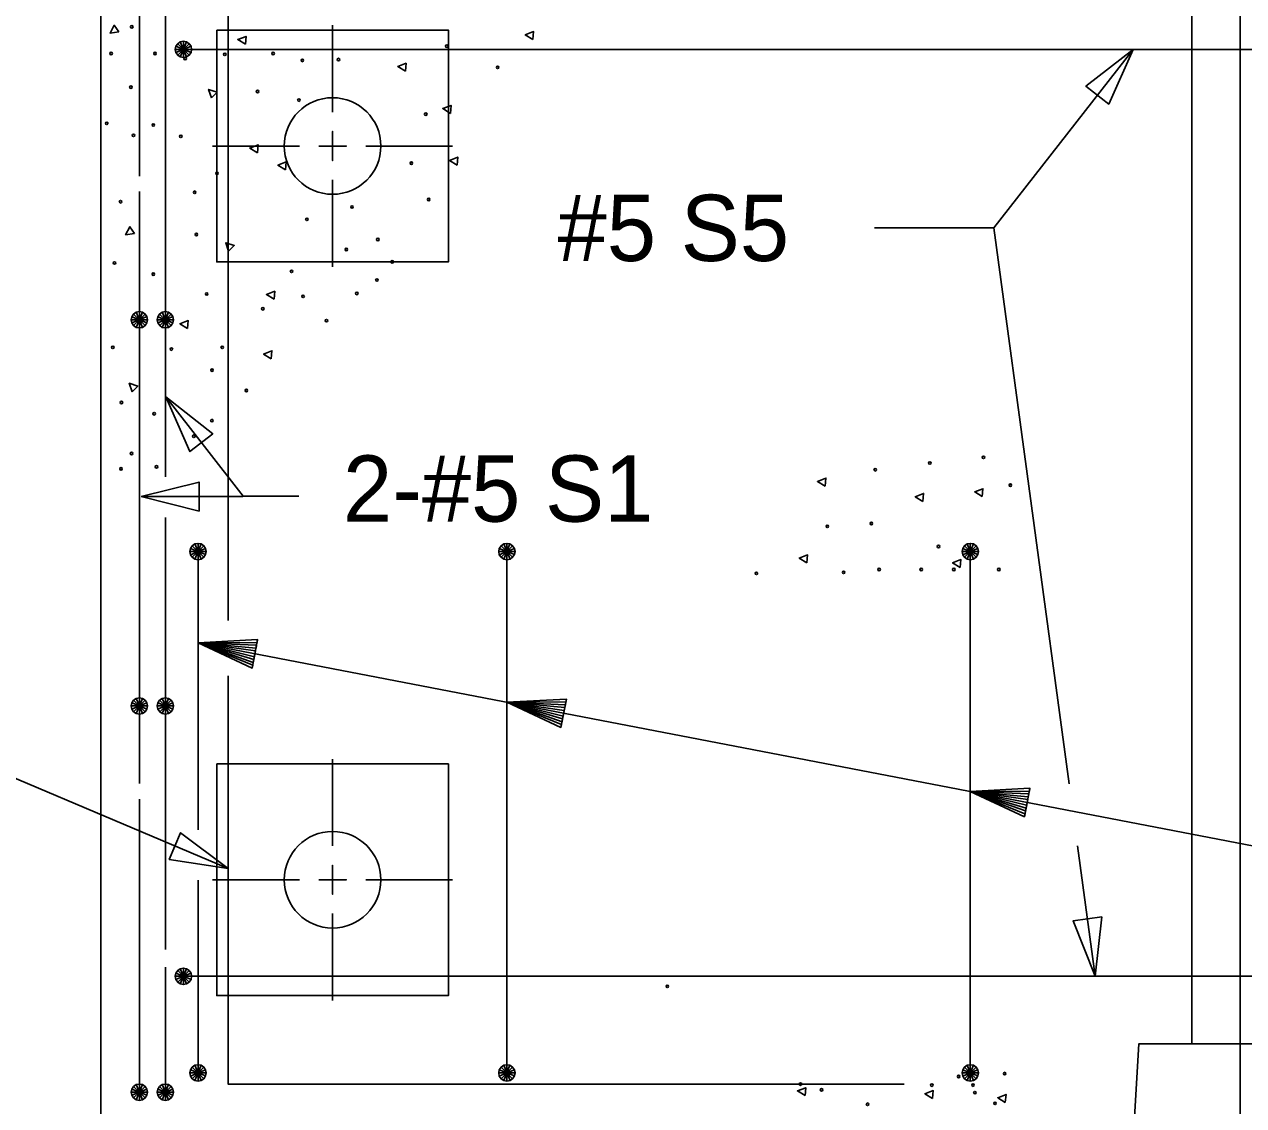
# Model space of a CAD drawing. Extents: x 0 to 177, y -1 to 127.
# Drawn here: x 141.301 to 143.931, y 47.847 to 50.18 of the extents above; entities that cross this region are included whole.
import ezdxf

# ---------------------------------------------------------------- set-up
doc = ezdxf.new("R2010")
doc.units = 0
for name, color, linetype in [('Arrowhead Terminators CELL', 7, 'Continuous'), ('Dimension Lines', 7, 'Continuous'), ('Mis Center Lines', 7, 'Continuous'), ('Rebar Lines', 7, 'Continuous'), ('Sup Concrete Girder Lines', 7, 'Continuous'), ('Sup Cored Slab Unit', 7, 'Continuous'), ('Text', 7, 'Continuous'), ('User Information Notes', 7, 'Continuous')]:
    doc.layers.add(name, color=color, linetype=linetype)

msp = doc.modelspace()

# ---------------------------------------------------------------- linework, layer by layer
at = {"layer": 'Arrowhead Terminators CELL'}
for points in [[(143.6929, 50.1259), (143.5913, 50.0466), (143.6406, 50.0081)], [(141.6057, 49.3762), (141.6577, 49.2583), (141.7071, 49.2966)], [(141.5526, 49.1609), (141.6776, 49.1297), (141.6776, 49.1922)], [(141.7406, 48.3582), (141.6377, 48.4357), (141.6133, 48.3782)], [(143.6113, 48.1259), (143.6254, 48.2539), (143.5635, 48.2455)]]:
    msp.add_lwpolyline(points, close=True, dxfattribs=at)
at = {"layer": 'Dimension Lines'}
for p, q in [((141.9656, 49.9905), (141.9656, 50.178)), ((141.894, 49.9175), (141.7065, 49.9175)), ((142.2246, 49.9175), (142.0371, 49.9175)), ((141.9656, 49.657), (141.9656, 49.8445)), ((143.3922, 49.7408), (143.5549, 48.5414)), ((141.7719, 49.1609), (141.5526, 49.1609)), ((141.9656, 48.4072), (141.9656, 48.5947)), ((143.5731, 48.4075), (143.6113, 48.1259)), ((141.894, 48.3342), (141.7065, 48.3342)), ((142.2246, 48.3342), (142.0371, 48.3342)), ((141.9656, 48.0737), (141.9656, 48.2612))]:
    msp.add_line(p, q, dxfattribs=at)
for points in [[(143.1348, 49.7408), (143.3922, 49.7408), (143.6929, 50.1259)], [(141.9357, 49.9175), (141.9656, 49.9175), (141.9955, 49.9175), (141.9656, 49.9175), (141.9656, 49.9489), (141.9656, 49.9175), (141.9656, 49.8862), (141.9656, 49.9175)], [(141.6057, 49.3762), (141.7724, 49.1616), (141.893, 49.1616)], [(141.7981, 48.8217), (141.797, 48.8156), (141.6754, 48.8453), (141.7957, 48.8094), (141.7946, 48.8033), (141.6754, 48.8453), (141.7934, 48.7972), (141.7922, 48.791), (141.6754, 48.8453), (141.804, 48.8524), (141.8029, 48.8462), (141.6754, 48.8453), (141.8016, 48.8401), (141.8005, 48.834), (141.6754, 48.8453), (141.7993, 48.8279), (141.7922, 48.791), (141.804, 48.8524), (141.6754, 48.8453), (141.7922, 48.791)], [(141.6754, 48.8453), (145.4224, 48.1242), (145.5342, 48.1242)], [(142.4644, 48.6935), (142.4633, 48.6873), (142.3417, 48.7171), (142.4621, 48.6812), (142.4609, 48.675), (142.3417, 48.7171), (142.4597, 48.6689), (142.4585, 48.6628), (142.3417, 48.7171), (142.4703, 48.7242), (142.4692, 48.718), (142.3417, 48.7171), (142.468, 48.7119), (142.4668, 48.7057), (142.3417, 48.7171), (142.4656, 48.6996), (142.4585, 48.6628), (142.4703, 48.7242), (142.3417, 48.7171), (142.4585, 48.6628)], [(140.796, 48.6638), (141.0193, 48.6638), (141.7406, 48.3582)], [(143.4644, 48.501), (143.4633, 48.4949), (143.3417, 48.5246), (143.4621, 48.4887), (143.4609, 48.4826), (143.3417, 48.5246), (143.4597, 48.4765), (143.4585, 48.4703), (143.3417, 48.5246), (143.4703, 48.5317), (143.4692, 48.5255), (143.3417, 48.5246), (143.468, 48.5194), (143.4668, 48.5133), (143.3417, 48.5246), (143.4656, 48.5072), (143.4585, 48.4703), (143.4703, 48.5317), (143.3417, 48.5246), (143.4585, 48.4703)], [(141.9357, 48.3342), (141.9656, 48.3342), (141.9955, 48.3342), (141.9656, 48.3342), (141.9656, 48.3655), (141.9656, 48.3342), (141.9656, 48.3028), (141.9656, 48.3342)]]:
    msp.add_lwpolyline(points, dxfattribs=at)
at = {"layer": 'Mis Center Lines'}
msp.add_line((143.9239, 47.6259), (143.9239, 50.6259), dxfattribs=at)
at = {"layer": 'Rebar Lines'}
for p, q in [((141.5489, 49.8527), (141.5489, 50.3759)), ((141.605, 49.2038), (141.605, 50.2242)), ((141.6439, 50.1259), (144.2689, 50.1259)), ((141.5489, 49.0027), (141.5489, 49.819)), ((141.605, 48.1837), (141.605, 49.1157)), ((141.6754, 48.4421), (141.6754, 49.0425)), ((142.3417, 47.9175), (142.3417, 49.0425)), ((143.3417, 47.9175), (143.3417, 49.0425)), ((141.5489, 48.542), (141.5489, 49.0027)), ((141.5489, 47.8759), (141.5489, 48.5083)), ((141.6754, 47.9175), (141.6754, 48.3332)), ((141.605, 47.8759), (141.605, 48.1458)), ((141.6439, 48.1259), (144.2689, 48.1259))]:
    msp.add_line(p, q, dxfattribs=at)
for points in [[(143.1991, 50.3594), (141.7406, 50.3594), (141.7406, 48.8938)], [(141.6263, 50.1259), (141.6276, 50.1326), (141.6314, 50.1383), (141.6371, 50.1422), (141.6439, 50.1435), (141.6506, 50.1422), (141.6564, 50.1383), (141.6602, 50.1326), (141.6615, 50.1259), (141.6602, 50.1191), (141.6564, 50.1134), (141.6507, 50.1096), (141.6439, 50.1082), (141.6371, 50.1096), (141.6315, 50.1134), (141.6276, 50.1191), (141.6263, 50.1259), (141.6439, 50.1259), (141.6615, 50.1259), (141.6602, 50.1326), (141.6439, 50.1259), (141.6564, 50.1383), (141.6506, 50.1422), (141.6439, 50.1259), (141.6439, 50.1435), (141.6371, 50.1422), (141.6439, 50.1259), (141.6314, 50.1383), (141.6276, 50.1326), (141.6439, 50.1259), (141.6276, 50.1191), (141.6315, 50.1134), (141.6439, 50.1259), (141.6371, 50.1096), (141.6439, 50.1082), (141.6439, 50.1259), (141.6507, 50.1096), (141.6564, 50.1134), (141.6439, 50.1259), (141.6602, 50.1191)], [(141.5313, 49.5425), (141.5326, 49.5492), (141.5364, 49.555), (141.5421, 49.5588), (141.5489, 49.5601), (141.5556, 49.5588), (141.5613, 49.555), (141.5651, 49.5493), (141.5665, 49.5425), (141.5651, 49.5358), (141.5613, 49.5301), (141.5556, 49.5262), (141.5489, 49.5249), (141.5421, 49.5262), (141.5364, 49.53), (141.5326, 49.5358), (141.5313, 49.5425), (141.5489, 49.5425), (141.5665, 49.5425), (141.5651, 49.5493), (141.5489, 49.5425), (141.5613, 49.555), (141.5556, 49.5588), (141.5489, 49.5425), (141.5489, 49.5601), (141.5421, 49.5588), (141.5489, 49.5425), (141.5364, 49.555), (141.5326, 49.5492), (141.5489, 49.5425), (141.5326, 49.5358), (141.5364, 49.53), (141.5489, 49.5425), (141.5421, 49.5262), (141.5489, 49.5249), (141.5489, 49.5425), (141.5556, 49.5262), (141.5613, 49.5301), (141.5489, 49.5425), (141.5651, 49.5358)], [(141.5874, 49.5425), (141.5887, 49.5492), (141.5925, 49.555), (141.5982, 49.5588), (141.605, 49.5601), (141.6117, 49.5588), (141.6175, 49.555), (141.6213, 49.5493), (141.6226, 49.5425), (141.6213, 49.5358), (141.6175, 49.5301), (141.6118, 49.5262), (141.605, 49.5249), (141.5982, 49.5262), (141.5926, 49.53), (141.5887, 49.5358), (141.5874, 49.5425), (141.605, 49.5425), (141.6226, 49.5425), (141.6213, 49.5493), (141.605, 49.5425), (141.6175, 49.555), (141.6117, 49.5588), (141.605, 49.5425), (141.605, 49.5601), (141.5982, 49.5588), (141.605, 49.5425), (141.5925, 49.555), (141.5887, 49.5492), (141.605, 49.5425), (141.5887, 49.5358), (141.5926, 49.53), (141.605, 49.5425), (141.5982, 49.5262), (141.605, 49.5249), (141.605, 49.5425), (141.6118, 49.5262), (141.6175, 49.5301), (141.605, 49.5425), (141.6213, 49.5358)], [(141.6578, 49.0425), (141.6591, 49.0492), (141.6629, 49.0549), (141.6686, 49.0588), (141.6754, 49.0601), (141.6821, 49.0588), (141.6878, 49.0549), (141.6916, 49.0492), (141.693, 49.0425), (141.6916, 49.0358), (141.6878, 49.03), (141.6821, 49.0262), (141.6754, 49.0248), (141.6686, 49.0262), (141.6629, 49.03), (141.6591, 49.0357), (141.6578, 49.0425), (141.6754, 49.0425), (141.693, 49.0425), (141.6916, 49.0492), (141.6754, 49.0425), (141.6878, 49.0549), (141.6821, 49.0588), (141.6754, 49.0425), (141.6754, 49.0601), (141.6686, 49.0588), (141.6754, 49.0425), (141.6629, 49.0549), (141.6591, 49.0492), (141.6754, 49.0425), (141.6591, 49.0357), (141.6629, 49.03), (141.6754, 49.0425), (141.6686, 49.0262), (141.6754, 49.0248), (141.6754, 49.0425), (141.6821, 49.0262), (141.6878, 49.03), (141.6754, 49.0425), (141.6916, 49.0358)], [(142.3241, 49.0425), (142.3254, 49.0492), (142.3292, 49.0549), (142.3349, 49.0588), (142.3417, 49.0601), (142.3484, 49.0588), (142.3541, 49.0549), (142.3579, 49.0492), (142.3593, 49.0425), (142.3579, 49.0358), (142.3541, 49.03), (142.3485, 49.0262), (142.3417, 49.0248), (142.3349, 49.0262), (142.3292, 49.03), (142.3254, 49.0357), (142.3241, 49.0425), (142.3417, 49.0425), (142.3593, 49.0425), (142.3579, 49.0492), (142.3417, 49.0425), (142.3541, 49.0549), (142.3484, 49.0588), (142.3417, 49.0425), (142.3417, 49.0601), (142.3349, 49.0588), (142.3417, 49.0425), (142.3292, 49.0549), (142.3254, 49.0492), (142.3417, 49.0425), (142.3254, 49.0357), (142.3292, 49.03), (142.3417, 49.0425), (142.3349, 49.0262), (142.3417, 49.0248), (142.3417, 49.0425), (142.3485, 49.0262), (142.3541, 49.03), (142.3417, 49.0425), (142.3579, 49.0358)], [(143.3241, 49.0425), (143.3254, 49.0492), (143.3292, 49.0549), (143.3349, 49.0588), (143.3417, 49.0601), (143.3484, 49.0588), (143.3541, 49.0549), (143.3579, 49.0492), (143.3593, 49.0425), (143.3579, 49.0358), (143.3541, 49.03), (143.3485, 49.0262), (143.3417, 49.0248), (143.3349, 49.0262), (143.3292, 49.03), (143.3254, 49.0357), (143.3241, 49.0425), (143.3417, 49.0425), (143.3593, 49.0425), (143.3579, 49.0492), (143.3417, 49.0425), (143.3541, 49.0549), (143.3484, 49.0588), (143.3417, 49.0425), (143.3417, 49.0601), (143.3349, 49.0588), (143.3417, 49.0425), (143.3292, 49.0549), (143.3254, 49.0492), (143.3417, 49.0425), (143.3254, 49.0357), (143.3292, 49.03), (143.3417, 49.0425), (143.3349, 49.0262), (143.3417, 49.0248), (143.3417, 49.0425), (143.3485, 49.0262), (143.3541, 49.03), (143.3417, 49.0425), (143.3579, 49.0358)], [(141.7406, 48.7744), (141.7406, 47.8928), (143.1991, 47.8928)], [(141.5313, 48.7092), (141.5326, 48.7159), (141.5364, 48.7216), (141.5421, 48.7255), (141.5489, 48.7268), (141.5556, 48.7255), (141.5613, 48.7216), (141.5651, 48.716), (141.5665, 48.7092), (141.5651, 48.7025), (141.5613, 48.6967), (141.5556, 48.6929), (141.5489, 48.6915), (141.5421, 48.6929), (141.5364, 48.6967), (141.5326, 48.7024), (141.5313, 48.7092), (141.5489, 48.7092), (141.5665, 48.7092), (141.5651, 48.716), (141.5489, 48.7092), (141.5613, 48.7216), (141.5556, 48.7255), (141.5489, 48.7092), (141.5489, 48.7268), (141.5421, 48.7255), (141.5489, 48.7092), (141.5364, 48.7216), (141.5326, 48.7159), (141.5489, 48.7092), (141.5326, 48.7024), (141.5364, 48.6967), (141.5489, 48.7092), (141.5421, 48.6929), (141.5489, 48.6915), (141.5489, 48.7092), (141.5556, 48.6929), (141.5613, 48.6967), (141.5489, 48.7092), (141.5651, 48.7025)], [(141.5874, 48.7092), (141.5887, 48.7159), (141.5925, 48.7216), (141.5982, 48.7255), (141.605, 48.7268), (141.6117, 48.7255), (141.6175, 48.7216), (141.6213, 48.716), (141.6226, 48.7092), (141.6213, 48.7025), (141.6175, 48.6967), (141.6118, 48.6929), (141.605, 48.6915), (141.5982, 48.6929), (141.5926, 48.6967), (141.5887, 48.7024), (141.5874, 48.7092), (141.605, 48.7092), (141.6226, 48.7092), (141.6213, 48.716), (141.605, 48.7092), (141.6175, 48.7216), (141.6117, 48.7255), (141.605, 48.7092), (141.605, 48.7268), (141.5982, 48.7255), (141.605, 48.7092), (141.5925, 48.7216), (141.5887, 48.7159), (141.605, 48.7092), (141.5887, 48.7024), (141.5926, 48.6967), (141.605, 48.7092), (141.5982, 48.6929), (141.605, 48.6915), (141.605, 48.7092), (141.6118, 48.6929), (141.6175, 48.6967), (141.605, 48.7092), (141.6213, 48.7025)], [(141.6263, 48.1259), (141.6276, 48.1326), (141.6314, 48.1383), (141.6371, 48.1422), (141.6439, 48.1435), (141.6506, 48.1422), (141.6564, 48.1383), (141.6602, 48.1326), (141.6615, 48.1259), (141.6602, 48.1191), (141.6564, 48.1134), (141.6507, 48.1096), (141.6439, 48.1082), (141.6371, 48.1096), (141.6315, 48.1134), (141.6276, 48.1191), (141.6263, 48.1259), (141.6439, 48.1259), (141.6615, 48.1259), (141.6602, 48.1326), (141.6439, 48.1259), (141.6564, 48.1383), (141.6506, 48.1422), (141.6439, 48.1259), (141.6439, 48.1435), (141.6371, 48.1422), (141.6439, 48.1259), (141.6314, 48.1383), (141.6276, 48.1326), (141.6439, 48.1259), (141.6276, 48.1191), (141.6315, 48.1134), (141.6439, 48.1259), (141.6371, 48.1096), (141.6439, 48.1082), (141.6439, 48.1259), (141.6507, 48.1096), (141.6564, 48.1134), (141.6439, 48.1259), (141.6602, 48.1191)], [(141.6578, 47.9175), (141.6591, 47.9242), (141.6629, 47.9299), (141.6686, 47.9338), (141.6754, 47.9351), (141.6821, 47.9338), (141.6878, 47.9299), (141.6916, 47.9242), (141.693, 47.9175), (141.6916, 47.9108), (141.6878, 47.905), (141.6821, 47.9012), (141.6754, 47.8998), (141.6686, 47.9012), (141.6629, 47.905), (141.6591, 47.9107), (141.6578, 47.9175), (141.6754, 47.9175), (141.693, 47.9175), (141.6916, 47.9242), (141.6754, 47.9175), (141.6878, 47.9299), (141.6821, 47.9338), (141.6754, 47.9175), (141.6754, 47.9351), (141.6686, 47.9338), (141.6754, 47.9175), (141.6629, 47.9299), (141.6591, 47.9242), (141.6754, 47.9175), (141.6591, 47.9107), (141.6629, 47.905), (141.6754, 47.9175), (141.6686, 47.9012), (141.6754, 47.8998), (141.6754, 47.9175), (141.6821, 47.9012), (141.6878, 47.905), (141.6754, 47.9175), (141.6916, 47.9108)], [(142.3241, 47.9175), (142.3254, 47.9242), (142.3292, 47.9299), (142.3349, 47.9338), (142.3417, 47.9351), (142.3484, 47.9338), (142.3541, 47.9299), (142.3579, 47.9242), (142.3593, 47.9175), (142.3579, 47.9108), (142.3541, 47.905), (142.3485, 47.9012), (142.3417, 47.8998), (142.3349, 47.9012), (142.3292, 47.905), (142.3254, 47.9107), (142.3241, 47.9175), (142.3417, 47.9175), (142.3593, 47.9175), (142.3579, 47.9242), (142.3417, 47.9175), (142.3541, 47.9299), (142.3484, 47.9338), (142.3417, 47.9175), (142.3417, 47.9351), (142.3349, 47.9338), (142.3417, 47.9175), (142.3292, 47.9299), (142.3254, 47.9242), (142.3417, 47.9175), (142.3254, 47.9107), (142.3292, 47.905), (142.3417, 47.9175), (142.3349, 47.9012), (142.3417, 47.8998), (142.3417, 47.9175), (142.3485, 47.9012), (142.3541, 47.905), (142.3417, 47.9175), (142.3579, 47.9108)], [(143.3241, 47.9175), (143.3254, 47.9242), (143.3292, 47.9299), (143.3349, 47.9338), (143.3417, 47.9351), (143.3484, 47.9338), (143.3541, 47.9299), (143.3579, 47.9242), (143.3593, 47.9175), (143.3579, 47.9108), (143.3541, 47.905), (143.3485, 47.9012), (143.3417, 47.8998), (143.3349, 47.9012), (143.3292, 47.905), (143.3254, 47.9107), (143.3241, 47.9175), (143.3417, 47.9175), (143.3593, 47.9175), (143.3579, 47.9242), (143.3417, 47.9175), (143.3541, 47.9299), (143.3484, 47.9338), (143.3417, 47.9175), (143.3417, 47.9351), (143.3349, 47.9338), (143.3417, 47.9175), (143.3292, 47.9299), (143.3254, 47.9242), (143.3417, 47.9175), (143.3254, 47.9107), (143.3292, 47.905), (143.3417, 47.9175), (143.3349, 47.9012), (143.3417, 47.8998), (143.3417, 47.9175), (143.3485, 47.9012), (143.3541, 47.905), (143.3417, 47.9175), (143.3579, 47.9108)], [(141.5313, 47.8759), (141.5326, 47.8826), (141.5364, 47.8883), (141.5421, 47.8922), (141.5489, 47.8935), (141.5556, 47.8922), (141.5613, 47.8883), (141.5651, 47.8826), (141.5665, 47.8759), (141.5651, 47.8691), (141.5613, 47.8634), (141.5556, 47.8596), (141.5489, 47.8582), (141.5421, 47.8596), (141.5364, 47.8634), (141.5326, 47.8691), (141.5313, 47.8759), (141.5489, 47.8759), (141.5665, 47.8759), (141.5651, 47.8826), (141.5489, 47.8759), (141.5613, 47.8883), (141.5556, 47.8922), (141.5489, 47.8759), (141.5489, 47.8935), (141.5421, 47.8922), (141.5489, 47.8759), (141.5364, 47.8883), (141.5326, 47.8826), (141.5489, 47.8759), (141.5326, 47.8691), (141.5364, 47.8634), (141.5489, 47.8759), (141.5421, 47.8596), (141.5489, 47.8582), (141.5489, 47.8759), (141.5556, 47.8596), (141.5613, 47.8634), (141.5489, 47.8759), (141.5651, 47.8691)], [(141.5873, 47.8759), (141.5886, 47.8826), (141.5924, 47.8883), (141.5981, 47.8922), (141.6049, 47.8935), (141.6116, 47.8922), (141.6174, 47.8883), (141.6212, 47.8826), (141.6225, 47.8759), (141.6212, 47.8691), (141.6174, 47.8634), (141.6117, 47.8596), (141.6049, 47.8582), (141.5981, 47.8596), (141.5925, 47.8634), (141.5886, 47.8691), (141.5873, 47.8759), (141.6049, 47.8759), (141.6225, 47.8759), (141.6212, 47.8826), (141.6049, 47.8759), (141.6174, 47.8883), (141.6116, 47.8922), (141.6049, 47.8759), (141.6049, 47.8935), (141.5981, 47.8922), (141.6049, 47.8759), (141.5924, 47.8883), (141.5886, 47.8826), (141.6049, 47.8759), (141.5886, 47.8691), (141.5925, 47.8634), (141.6049, 47.8759), (141.5981, 47.8596), (141.6049, 47.8582), (141.6049, 47.8759), (141.6117, 47.8596), (141.6174, 47.8634), (141.6049, 47.8759), (141.6212, 47.8691)]]:
    msp.add_lwpolyline(points, dxfattribs=at)
at = {"layer": 'Sup Concrete Girder Lines'}
for p, q in [((141.4656, 47.6259), (141.4656, 50.6259)), ((143.8197, 47.98), (143.8197, 50.6259))]:
    msp.add_line(p, q, dxfattribs=at)
for points in [[(141.5047, 50.164), (141.4947, 50.1782), (141.4856, 50.1612), (141.5047, 50.164)], [(141.7774, 50.137), (141.7789, 50.1541), (141.7609, 50.1471), (141.7774, 50.137)], [(142.3978, 50.1473), (142.3993, 50.1645), (142.3813, 50.1574), (142.3978, 50.1473)], [(142.1227, 50.079), (142.1242, 50.0962), (142.1063, 50.0891), (142.1227, 50.079)], [(141.7041, 50.0213), (141.7164, 50.0335), (141.698, 50.0396), (141.7041, 50.0213)], [(142.2199, 49.988), (142.2214, 50.0052), (142.2034, 49.9982), (142.2199, 49.988)], [(141.8034, 49.9029), (141.8049, 49.9202), (141.7869, 49.913), (141.8034, 49.9029)], [(141.8642, 49.866), (141.8657, 49.8832), (141.8478, 49.8761), (141.8642, 49.866)], [(142.2344, 49.8764), (142.2359, 49.8936), (142.2179, 49.8865), (142.2344, 49.8764)], [(141.5382, 49.729), (141.5282, 49.7432), (141.519, 49.7262), (141.5382, 49.729)], [(141.7413, 49.6903), (141.7536, 49.7026), (141.7352, 49.7087), (141.7413, 49.6903)], [(141.8394, 49.5869), (141.8409, 49.604), (141.8229, 49.597), (141.8394, 49.5869)], [(141.6529, 49.5237), (141.6543, 49.5409), (141.6364, 49.5338), (141.6529, 49.5237)], [(141.8332, 49.4586), (141.8347, 49.4758), (141.8167, 49.4687), (141.8332, 49.4586)], [(141.5331, 49.3873), (141.5454, 49.3996), (141.527, 49.4057), (141.5331, 49.3873)], [(143.0285, 49.1836), (143.03, 49.2008), (143.012, 49.1937), (143.0285, 49.1836)], [(143.3676, 49.1609), (143.3691, 49.178), (143.3512, 49.171), (143.3676, 49.1609)], [(143.2394, 49.1505), (143.2409, 49.1677), (143.223, 49.1606), (143.2394, 49.1505)], [(142.9892, 49.0182), (142.9907, 49.0353), (142.9727, 49.0283), (142.9892, 49.0182)], [(143.3201, 49.0078), (143.3216, 49.025), (143.3036, 49.0179), (143.3201, 49.0078)], [(143.6843, 47.6259), (143.7052, 47.98), (144.1427, 47.98), (144.1635, 47.6259)], [(142.9851, 47.8684), (142.9866, 47.8855), (142.9686, 47.8785), (142.9851, 47.8684)], [(143.2601, 47.8622), (143.2616, 47.8794), (143.2437, 47.8723), (143.2601, 47.8622)], [(143.4172, 47.8539), (143.4188, 47.8711), (143.4008, 47.864), (143.4172, 47.8539)]]:
    msp.add_lwpolyline(points, dxfattribs=at)
for centre, radius in [((141.5323, 50.1747), 0.00273), ((141.4877, 50.117), 0.00273), ((141.5826, 50.117), 0.00273), ((141.7332, 50.1152), 0.00273), ((141.8373, 50.117), 0.00273), ((142.2122, 50.1329), 0.00273), ((141.6476, 50.1059), 0.00273), ((141.9005, 50.1022), 0.00273), ((141.9785, 50.104), 0.00273), ((142.3218, 50.0874), 0.00273), ((141.5305, 50.0445), 0.00273), ((141.8038, 50.0352), 0.00273), ((141.9656, 49.9175), 0.1042), ((141.893, 50.0166), 0.00273), ((142.1667, 49.9861), 0.00273), ((141.4784, 49.9664), 0.00273), ((141.5788, 49.9627), 0.00273), ((141.5361, 49.9404), 0.00273), ((141.6383, 49.9385), 0.00273), ((142.1357, 49.8806), 0.00273), ((141.7164, 49.8586), 0.00273), ((141.6681, 49.8177), 0.00273), ((142.173, 49.8021), 0.00273), ((141.5082, 49.7972), 0.00273), ((142.0075, 49.786), 0.00273), ((141.9103, 49.7592), 0.00273), ((141.6718, 49.7266), 0.00273), ((141.9953, 49.6943), 0.00273), ((142.0633, 49.7157), 0.00273), ((141.4952, 49.6652), 0.00273), ((141.8772, 49.647), 0.00273), ((142.0944, 49.6676), 0.00273), ((141.5788, 49.6411), 0.00273), ((142.0613, 49.6283), 0.00273), ((141.6941, 49.5983), 0.00273), ((141.902, 49.5932), 0.00273), ((142.0179, 49.5994), 0.00273), ((141.8152, 49.5663), 0.00273), ((141.9525, 49.5407), 0.00273), ((141.4914, 49.483), 0.00273), ((141.6179, 49.4793), 0.00273), ((141.7276, 49.483), 0.00273), ((141.7056, 49.4339), 0.00273), ((141.7796, 49.39), 0.00273), ((141.51, 49.364), 0.00273), ((141.5807, 49.3398), 0.00273), ((141.7053, 49.325), 0.00273), ((141.6663, 49.2912), 0.00273), ((141.5319, 49.254), 0.00273), ((141.5091, 49.2209), 0.00273), ((141.5856, 49.2251), 0.00273), ((143.2545, 49.2334), 0.00273), ((143.3703, 49.2458), 0.00273), ((143.1366, 49.2189), 0.00273), ((143.4282, 49.1858), 0.00273), ((143.0332, 49.0969), 0.00273), ((143.1283, 49.103), 0.00273), ((143.2731, 49.0534), 0.00273), ((142.8802, 48.9955), 0.00273), ((143.0684, 48.9976), 0.00273), ((143.1449, 49.0038), 0.00273), ((143.2359, 49.0038), 0.00273), ((143.3062, 49.0038), 0.00273), ((143.4034, 49.0038), 0.00273), ((141.9656, 48.3342), 0.1042), ((142.6879, 48.1042), 0.00273), ((143.3166, 47.9098), 0.00273), ((143.4158, 47.916), 0.00273), ((142.9753, 47.8933), 0.00273), ((143.0208, 47.8809), 0.00273), ((143.2587, 47.8912), 0.00273), ((143.3476, 47.8912), 0.00273), ((143.3517, 47.8747), 0.00273), ((143.1201, 47.8498), 0.00273), ((143.3951, 47.8519), 0.00273)]:
    msp.add_circle(centre, radius, dxfattribs=at)
at = {"layer": 'Sup Cored Slab Unit'}
for points in [[(141.7156, 50.1675), (142.2156, 50.1675), (142.2156, 49.6675), (141.7156, 49.6675)], [(141.7156, 48.5842), (142.2156, 48.5842), (142.2156, 48.0842), (141.7156, 48.0842)]]:
    msp.add_lwpolyline(points, close=True, dxfattribs=at)
at = {"layer": 'User Information Notes'}
msp.add_line((141.605, 47.8759), (141.605, 47.8759), dxfattribs=at)

# ---------------------------------------------------------------- texts
at = {"layer": 'Text'}
for s, p in [('#5 S5', (142.451, 49.6693)), ('2-#5 S1', (141.9881, 49.1068))]:
    msp.add_text(s, height=0.14302, dxfattribs=at).set_placement(p)

doc.saveas('drawing.dxf')
